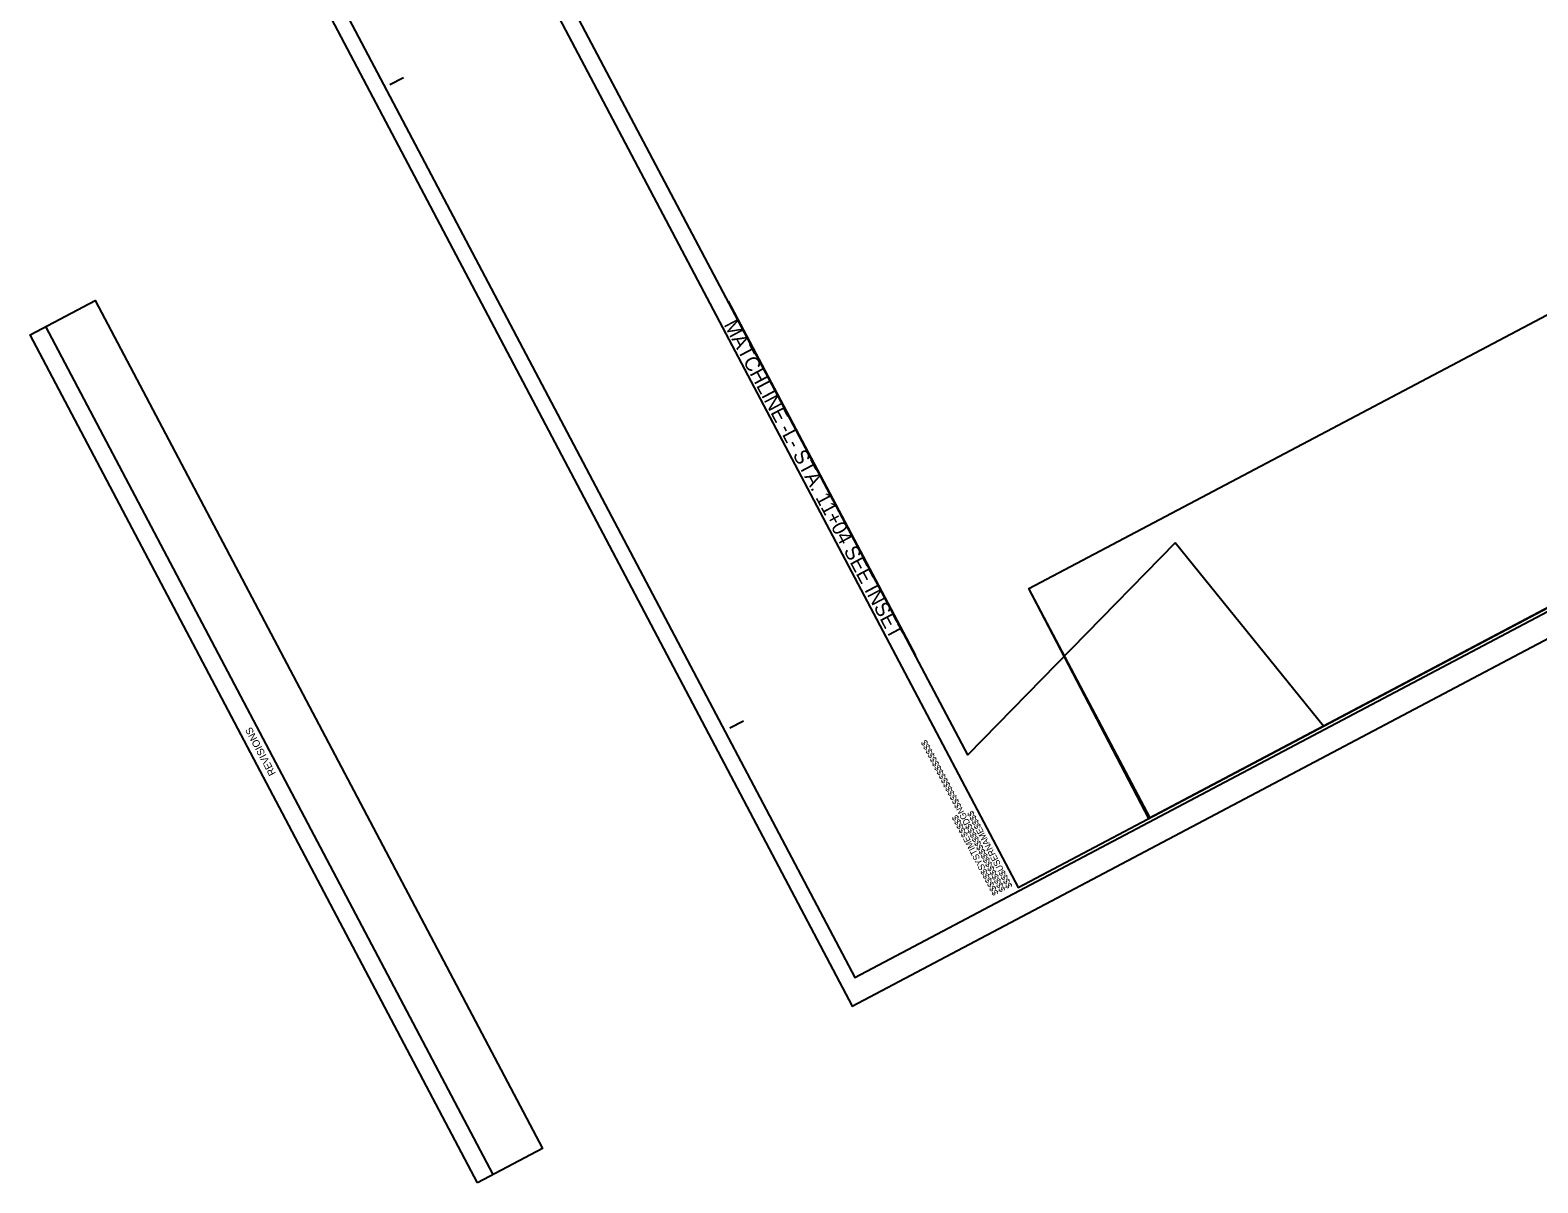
# Model space of a CAD drawing. Extents: x 1487176 to 1489663, y 497841 to 500965.
# Drawn here: x 1487176 to 1488420, y 497841 to 498792 of the extents above; entities that cross this region are included whole.
import ezdxf

# ---------------------------------------------------------------- set-up
doc = ezdxf.new("R2010")
doc.units = 0
for name, color, linetype in [('DEV TUBULAR MARKER PLAN VIEW CELL', 7, 'Continuous'), ('MARK STRAIGHT ARROW CELL', 7, 'Continuous'), ('Prop Mkg 3ft Min Skp 9ft White', 7, 'Continuous'), ('Prop Mkg Min Skp 6ft White', 7, 'Continuous'), ('Prop Mkg Solid Dbl Yel Rpm 80ft', 7, 'Continuous'), ('Prop Mkg Solid White Crosswalks', 7, 'Continuous'), ('Prop Mkg Solid White Lane Line', 7, 'Continuous'), ('Prop Paint Stripe', 7, 'Continuous'), ('Scratch_Level_1', 7, 'Continuous')]:
    doc.layers.add(name, color=color, linetype=linetype)

msp = doc.modelspace()

# ---------------------------------------------------------------- linework, layer by layer
at = {"layer": 'DEV TUBULAR MARKER PLAN VIEW CELL'}
for points in [[(1488120.4, 498369.2), (1487949.5, 498194.2), (1487512.6, 499019.7), (1488662.1, 499625.8), (1488771.3, 499418.8), (1488936.6, 499506), (1489317.2, 498785.2), (1488242.7, 498217.8)], [(1489217.3, 498974.3), (1489217.3, 498974.3), (1489317.2, 498785.2), (1488872, 498550.1), (1488513.2, 498414), (1488535.2, 498372.3), (1488098.7, 498141.8), (1487999.8, 498331.5)]]:
    msp.add_lwpolyline(points, close=True, dxfattribs=at)
at = {"layer": 'MARK STRAIGHT ARROW CELL'}
msp.add_lwpolyline([(1488830.6, 499742), (1487342.4, 498956.2), (1487854.1, 497987.1), (1489342.3, 498772.9)], close=True, dxfattribs=at)
at = {"layer": 'Prop Mkg 3ft Min Skp 9ft White'}
msp.add_line((1487751.6, 498568.2), (1487906.2, 498276.2), dxfattribs=at)
at = {"layer": 'Prop Mkg Min Skp 6ft White'}
msp.add_line((1487557.9, 497848.3), (1487188.7, 498547.4), dxfattribs=at)
msp.add_lwpolyline([(1487545, 497841.5), (1487175.9, 498540.6), (1487229.4, 498568.9), (1487598.6, 497869.7)], close=True, dxfattribs=at)
at = {"layer": 'Prop Mkg Solid Dbl Yel Rpm 80ft'}
for p, q in [((1487856.2, 498010.8), (1487856.2, 498010.8)), ((1487854.1, 497987.1), (1487854.1, 497987.1))]:
    msp.add_line(p, q, dxfattribs=at)
at = {"layer": 'Prop Mkg Solid White Lane Line'}
for points in [[(1488826.9, 499713.7), (1487500.5, 499013.3), (1487990.8, 498084.8), (1489317.2, 498785.2)], [(1487999.8, 498331.5), (1489217.3, 498974.3), (1489317.2, 498785.2), (1488099.7, 498142.3)]]:
    msp.add_lwpolyline(points, close=True, dxfattribs=at)
at = {"layer": 'Scratch_Level_1'}
for p, q in [((1487472.7, 498746.9), (1487483.8, 498752.8)), ((1487753.1, 498216.5), (1487764.2, 498222.3))]:
    msp.add_line(p, q, dxfattribs=at)
msp.add_lwpolyline([(1488835.9, 499722.2), (1487363.2, 498944.6), (1487856.2, 498010.8), (1489329, 498788.5)], close=True, dxfattribs=at)

# ---------------------------------------------------------------- texts
at = {"layer": 'Prop Mkg Min Skp 6ft White'}
msp.add_text('REVISIONS', height=6, rotation=117.8351, dxfattribs=at).set_placement((1487378.7, 498179))
at = {"layer": 'Prop Mkg Solid White Crosswalks'}
msp.add_text('MATCHLINE -L- STA. 11+04 SEE INSET', height=12, rotation=297.9716, dxfattribs=at).set_placement((1487747.8, 498549))
at = {"layer": 'Prop Paint Stripe'}
for s, p in [('$$$$$$$$$$$$$$$$DGN$$$$$$$$$$$$$$$$', (1487980.7, 498082.8)), ('$$$$USERNAME$$$$', (1487986.4, 498085.9)), ('$$$$$$SYSTIME$$$$$', (1487975, 498080))]:
    msp.add_text(s, height=5.25, rotation=117.8351, dxfattribs=at).set_placement(p)

doc.saveas('drawing.dxf')
